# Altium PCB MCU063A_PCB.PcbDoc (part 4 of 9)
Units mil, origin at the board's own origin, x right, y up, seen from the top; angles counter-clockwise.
Board outline 4165.01 x 2371.03 mil, 10 copper layers (Top Layer, Internal Plane 2, Signal Layer 3, Signal Layer 4, Internal Plane 5, Internal Plane 6, Signal Layer 7, Signal Layer 8, Internal Plane 9, Bottom), stack 59.9 mil thick; 436 components, 392 nets, 1750 pads, 1250 vias.
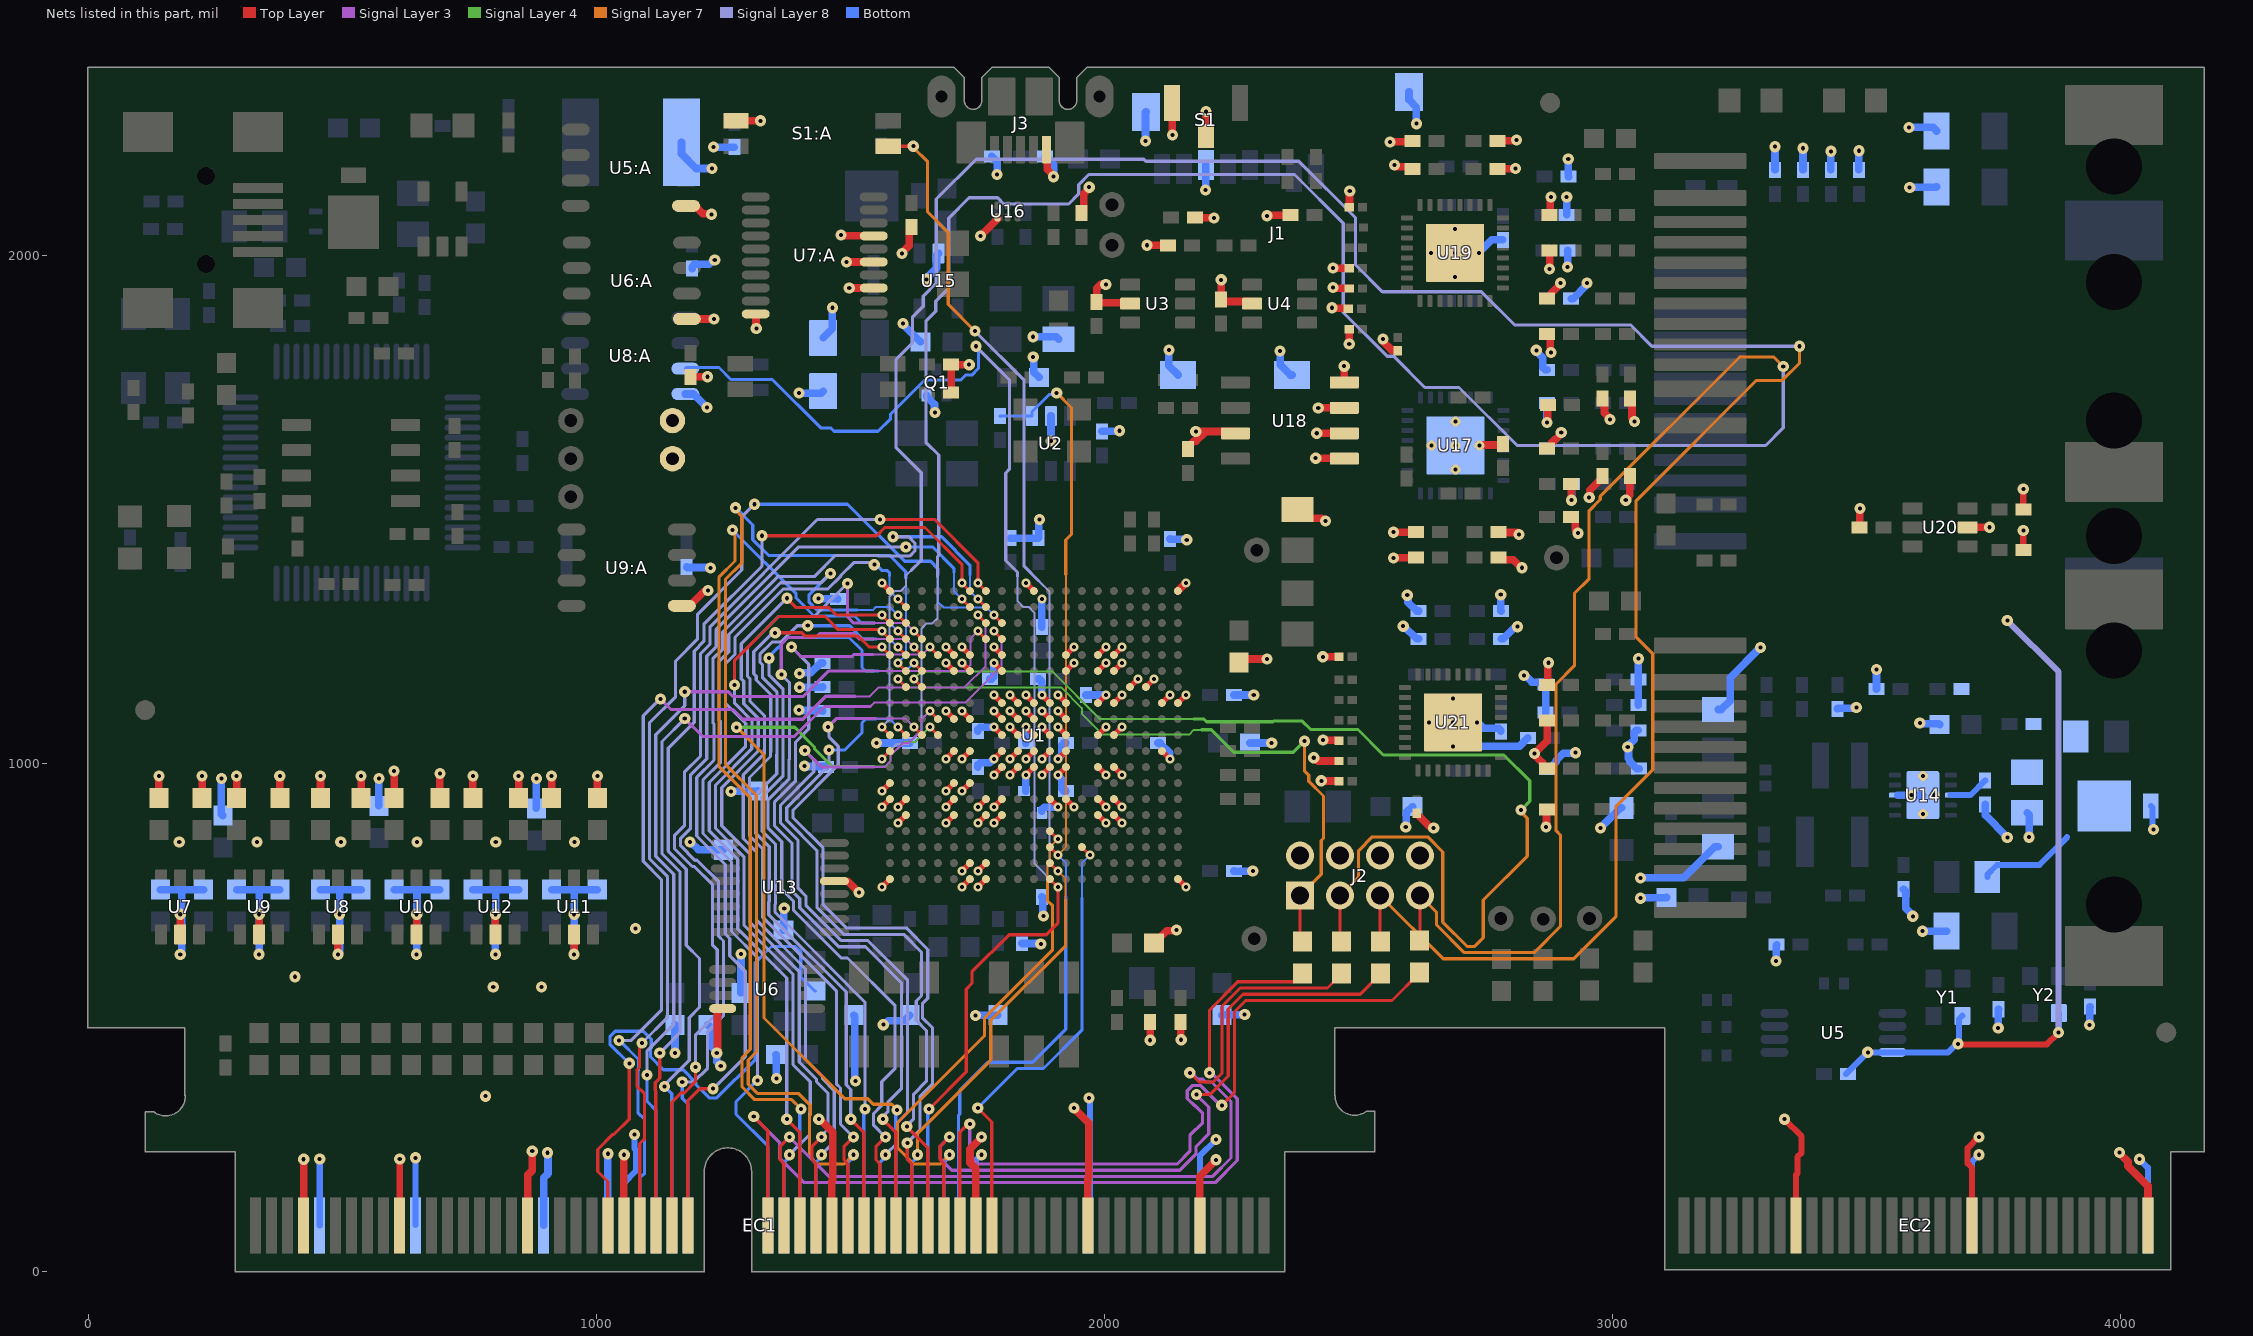
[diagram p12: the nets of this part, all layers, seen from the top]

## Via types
v1: diameter 22, hole 8, Top Layer to Bottom, tented both sides, 895 vias
v2: diameter 18, hole 8, Top Layer to Bottom, tented both sides, 334 vias
v3: diameter 19.68, hole 7.87, Top Layer to Bottom, 19 vias
v4: diameter 18/18/18/18/18/18 (per signal layer), hole 8, Top Layer to Bottom, tented both sides, 1 vias
v5: diameter 22/22/22/22/22/22 (per signal layer), hole 8, Top Layer to Bottom, tented both sides, 1 vias

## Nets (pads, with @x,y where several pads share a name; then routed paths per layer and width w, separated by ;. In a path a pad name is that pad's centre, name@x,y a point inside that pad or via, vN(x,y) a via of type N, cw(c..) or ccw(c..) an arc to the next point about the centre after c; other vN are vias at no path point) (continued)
GND: C1.2 C2.2 C3.2 C4.2 C5.2 C6.2 C7.2 C8.2 C9.2 C10.2 C11.2 C12.2 C13.2 C14.2 C15.2 C16.2 C17.2 C18.2 C19.2 C20.2 C21.2 C21:A.2 C22.2 C23.2 C23:A.2 C24.2 C24:A.1 C25.2 C26.2 C26:A.2 C27.2 C28.2 C28:A.2 C29.2 C29:A.1 C30.2 C31.2 C32.2 C33.2 C34.2 C35.2 C36.2 C37.2 C38.2 C39.2 C40.2 C41.2 C42.2 C43.2 C44.1 C45.2 C46.2 C47.2 C48.2 C49.1 C51.2 C52.1 C53.1 C54.2 C55.2 C56.2 C57.2 C58.2 C59.2 C60.2 C61.2 C62.2 C63.1 C64.1 C65.2 C66.2 C67.2 C68.2 C69.2 C70.2 C71.2 C72.2 C73.2 C74.2 C75.2 C76.2 C77.2 C78.2 C79.2 C80.2 C81.1 C82.2 C83.2 C84.2 C85.2 C86.1 C87.2 C88.2 C89.2 C90.2 C91.2 C92.2 C93.2 C94.2 C95.2 C96.2 C97.1 C98.1 C99.1 C100.1 C101.2 C102.2 C103.1 C104.2 C105.2 C106.2 C107.2 C108.2 C109.2 C110.2 C111.2 C112.2 C113.2 C114.1 C115.2 C116.1 C117.1 C118.1 C119.2 C120.2 C121.1 C122.2 C123.2 C124.2 C125.2 C126.2 C127.2 C128.2 C129.2 C130.2 C131.2 C132.1 C133.1 C134.2 C135.1 C136.1 C137.2 C138.2 C139.1 D5.1 EC1.7 EC1.10 EC1.19 EC1.22 EC1.35 EC1.38 EC1.46 EC1.47 EC1.65 EC1.83 EC1.97 EC1.111 EC2.135 EC2.157 EC2.179 J1.6 J1.S1 J1.S2 J1.S3 J1.S4 J2.2 J2.4 J2.6 J2.8 J3.5 Q1.2 R16.1 R17.1 R18.1 R29.2 R30.1 R38.2 R42.2 R43.2 R88.1 R89.1 R90.1 R96.1 R101.2 R102.2 R105.2 R120.2 R127.1 R128.1 R129.1 R130.1 R131.1 R132.1 R139.2 R140.2 R144.2 R151.1 R152.1 R153.1 R154.1 R155.1 S1.2 S1.3 S1:A.1 TP10.1 U1.A1 U1.A10 U1.A19 U1.E5 U1.E6 U1.E8 U1.E12 U1.E14 U1.E15 U1.F5 U1.F6 U1.F8 U1.F12 U1.F14 U1.F15 U1.G16 U1.G17 U1.H8 U1.H9 U1.H10 U1.H11 U1.H12 U1.H14 U1.H15 U1.H18 U1.H19 U1.J5 U1.J6 U1.J8 U1.J9 U1.J10 U1.J11 U1.J12 U1.K8 U1.K9 U1.K10 U1.K11 U1.K12 U1.K14 U1.K15 U1.L5 U1.L6 U1.L8 U1.L9 U1.L10 U1.L11 U1.L12 U1.L18 U1.M8 U1.M9 U1.M10 U1.M11 U1.M12 U1.M14 U1.M15 U1.N1 U1.N5 U1.N6 U1.P1 U1.P2 U1.P5 U1.P7 U1.P8 U1.P11 U1.P12 U1.P14 U1.P15 U1.R2 U1.R5 U1.R7 U1.R8 U1.R14 U1.R15 U1.V6 U1.V7 U1.W1 U1.W6 U1.W7 U1.W19 U2.2 U3.2 U4.2 U5.4 U5:A.5 U6.4 U6:A.5 U7.2 U7:A.10 U7:A.13 U7:A.15 U7:A.17 U8.2 U8:A.4 U9.2 U9:A.5 U10.2 U11.2 U12.2 U13.13 U14.8 U14.11 U15.2 U16.4 U17.33@2691.07,1626.06 U18.1 U18.2 U18.3 U18.4 U18.7 U19.33@2690.01,2005 U20.2 U21.33@2686.07,1081.06 Y1.2 Y2.2 | length 16818.5
  Top Layer w10: v2(1562.21,756.89) U1.W1@1577.96,772.63 ; v2(1562.21,914.37) U1.P1@1577.96,930.12 ; v2(1562.21,945.86) U1.N1@1577.96,961.61 ; v2(1562.21,1355.31) U1.A1@1577.96,1339.56 ; v2(1593.7,882.87) U1.R2@1609.45,898.62 ; v2(1593.7,914.37) U1.P2@1609.45,930.12 ; v2(1688.19,882.87) U1.R5@1703.94,898.62 ; v2(1688.19,914.37) U1.P5@1703.94,930.12 ; v2(1688.19,945.86) U1.N5@1703.94,961.61 ; v2(1688.19,1008.86) U1.L5@1703.94,1024.6 ; v2(1688.19,1103.34) U1.J5@1703.94,1087.6 ; v2(1688.19,1197.83) U1.F5@1703.94,1182.08 ; v2(1688.19,1229.33) U1.E5@1703.94,1213.58 ; v2(1719.69,756.89) U1.W6@1735.44,772.63 ; v2(1719.69,788.38) U1.V6@1735.44,804.13 ; v2(1719.69,945.86) U1.N6@1735.44,961.61 ; v2(1719.69,1008.86) U1.L6@1735.44,1024.6 ; v2(1719.69,1103.34) U1.J6@1735.44,1087.6 ; v2(1719.69,1197.83) U1.F6@1735.44,1182.08 ; v2(1719.69,1229.33) U1.E6@1735.44,1213.58 ; v2(1751.18,756.89) U1.W7@1766.93,772.63 ; v2(1751.18,788.38) U1.V7@1766.93,804.13 ; v2(1751.18,882.87) U1.R7@1766.93,898.62 ; v2(1751.18,914.37) U1.P7@1766.93,930.12 ; v2(1782.68,882.87) U1.R8@1798.43,898.62 ; v2(1782.68,914.37) U1.P8@1798.43,930.12 ; v2(1782.68,977.36) U1.M8@1798.43,993.11 ; v2(1782.68,1008.86) U1.L8@1798.43,1024.6 ; v2(1782.68,1071.85) U1.K8@1798.43,1056.1 ; v2(1782.68,1103.34) U1.J8@1798.43,1087.6 ; v2(1782.68,1134.84) U1.H8@1798.43,1119.09 ; v2(1782.68,1197.83) U1.F8@1798.43,1182.08 ; v2(1782.68,1229.33) U1.E8@1798.43,1213.58 ; v2(1814.18,977.36) U1.M9@1829.92,993.11 ; v2(1814.18,1008.86) U1.L9@1829.92,1024.6 ; v2(1814.18,1071.85) U1.K9@1829.92,1056.1 ; v2(1814.18,1103.34) U1.J9@1829.92,1087.6 ; v2(1814.18,1134.84) U1.H9@1829.92,1119.09 ; v2(1845.67,977.36) U1.M10@1861.42,993.11 ; v2(1845.67,1008.86) U1.L10@1861.42,1024.6 ; v2(1845.67,1071.85) U1.K10@1861.42,1056.1 ; v2(1845.67,1103.34) U1.J10@1861.42,1087.6 ; v2(1845.67,1134.84) U1.H10@1861.42,1119.09 ; v2(1845.67,1355.31) U1.A10@1861.42,1339.56 ; v2(1877.17,977.36) U1.M11@1892.92,993.11 ; v2(1877.17,1008.86) U1.L11@1892.92,1024.6 ; v2(1877.17,1071.85) U1.K11@1892.92,1056.1 ; v2(1877.17,1103.34) U1.J11@1892.92,1087.6 ; v2(1877.17,1134.84) U1.H11@1892.92,1119.09 ; U1.P11@1892.92,930.12 v2(1908.66,914.37) ; v2(1908.66,977.36) U1.M12@1924.41,993.11 ; v2(1908.66,1008.86) U1.L12@1924.41,1024.6 ; v2(1908.66,1071.85) U1.K12@1924.41,1056.1 ; v2(1908.66,1103.34) U1.J12@1924.41,1087.6 ; v2(1908.66,1134.84) U1.H12@1924.41,1119.09 ; U1.P12@1924.41,930.12 v2(1940.16,914.37) ; U1.F12@1924.41,1182.08 v2(1940.16,1197.83) ; U1.E12@1924.41,1213.58 v2(1940.16,1229.33) ; U1.R14@1987.4,898.62 v2(2003.15,882.87) ; U1.P14@1987.4,930.12 v2(2003.15,914.37) ; U1.M14@1987.4,993.11 v2(2003.15,977.36) ; U1.K14@1987.4,1056.1 v2(2003.15,1071.85) ; U1.H14@1987.4,1119.09 v2(2003.15,1134.84) ; U1.F14@1987.4,1182.08 v2(2003.15,1197.83) ; U1.E14@1987.4,1213.58 v2(2003.15,1229.33) ; U1.R15@2018.9,898.62 v2(2034.65,882.87) ; U1.P15@2018.9,930.12 v2(2034.65,914.37) ; U1.M15@2018.9,993.11 v2(2034.65,977.36) ; U1.K15@2018.9,1056.1 v2(2034.65,1071.85) ; U1.H15@2018.9,1119.09 v2(2034.65,1134.84) ; U1.F15@2018.9,1182.08 v2(2034.65,1197.83) ; U1.E15@2018.9,1213.58 v2(2034.65,1229.33) ; U1.G16@2050.4,1150.59 v2(2066.14,1166.34) ; U1.G17@2081.89,1150.59 v2(2097.64,1166.34) ; U1.L18@2113.39,1024.6 v2(2129.14,1008.86) ; U1.H18@2113.39,1119.09 v2(2129.14,1134.84) ; U1.W19@2144.88,772.63 v2(2160.63,756.89) ; U1.H19@2144.88,1119.09 v4(2160.63,1134.84)
  Top Layer w12: EC1.19@613.19,91 v1(613.19,221.82) ; v1(3338.36,300) 3372.21,266.15 3372.21,233.97 3363.9,225.66 3363.9,193.01 3361.13,190.24 EC2.135@3361.13,91 EC2.135@3363.9,93.77 ; v1(3680.21,448.31) 3681.21,447.31 3855.21,447.31 v1(3878.21,470.31) ; EC2.157@3707.59,91 3707.59,204.93 3699.21,213.31 3699.21,242.9 v1(3721.31,265) ; R139.2@3808.63,1420 v1(3808.63,1458.62) ; R140.2@3808.63,1500 v1(3808.63,1540.62)
  Top Layer w15: C33.2@139.21,931.81 v1(139.21,975.31) ; U7.2@181.02,663.74 181.02,703.12 v1(181.21,703.31) ; C17.2@224.21,931.81 v1(224.21,975.31) ; C37.2@292.21,931.81 v1(292.21,975.31) ; U9.2@336.42,663.74 v1@336.42,703.12 ; C21.2@377.21,931.81 v1(377.21,975.31) ; EC1.7@424.22,91 v1(424.22,221.21) ; C35.2@457.21,931.81 v1(457.21,975.31) ; v1(491.42,624.5) U8.2@491.42,663.74 ; C19.2@537.21,931.81 v1(537.21,975.31) ; C39.2@602.21,931.81 v1(602.21,985.31) ; U10.2@646.42,663.74 v1@646.42,703.12 ; C23.2@692.21,931.81 v1(692.21,980.31) ; C43.2@757.21,931.81 v1(757.21,975.31) ; U12.2@801.42,663.74 v1@801.42,703.12 ; C27.2@847.21,931.81 v1(847.21,975.31) ; EC1.35@865.16,91 865.16,190.15 874.01,199 v1(874.01,237) ; C41.2@912.21,931.81 v1(912.21,975.31) ; v1(956.42,624.5) U11.2@956.42,663.74 ; C25.2@1002.21,931.81 v1(1002.21,975.31) ; EC1.47@1054.14,91 1054.14,229.13 v1(1055.01,230) ; U9:A.5@1168.51,1310.32 1184.2,1310.32 1212.86,1338.97 1218.87,1338.97 v1(1220.21,1340.31) ; U5:A.5@1176.68,2097.63 1194.7,2097.63 1210,2082.34 1225.67,2082.34 v1(1227.01,2081) ; U6:A.5@1178.51,1875 v1(1232.01,1875) ; C26:A.2@1185.03,1761.23 v1(1218.78,1761.23) ; v1@1238.55,432.03 1238.55,516.46 1239.8,517.71 U6.4@1248.82,517.71 ; S1:A.1@1275.01,2265 v1(1323.01,2265) ; U7:A.10@1313.87,1884.84 1314.44,1884.27 1314.44,1856.57 v1(1315.01,1856) ; v1(1438.04,300) 1439.86,300 1465.54,274.32 1465.54,180.53 1463.59,178.58 EC1.65@1463.59,91 ; U13.13@1468.7,768.6 1468.85,768.46 1494.74,768.46 1516.89,746.31 v1(1517.21,746.31) ; v1(1482.01,2040) 1483.1,2038.91 1545.63,2038.91 U7:A.17@1546.15,2038.39 ; v1(1492.8,1987.2) U7:A.15@1546.15,1987.2 ; v1(1497.99,1936.02) U7:A.13@1546.15,1936.02 ; v1(1602.01,2004) 1602.01,2005.89 1615.7,2019.58 1615.7,2052.07 C24:A.1@1620.01,2056.38 ; R29.2@1698.63,1730 R30.1@1698.63,1785 v1(1734.01,1785) ; EC1.83@1747.05,91 1747.05,202.96 1735.5,214.51 1735.5,240.61 1758,263.11 v1(1758,265) ; v1(1756.01,2038) 1790.01,2072 U16.4@1790.01,2075 ; J3.5@1886.14,2207.75 1887.49,2206.39 1887.49,2169.41 1900.01,2156.89 v1(1900.01,2155) ; v1(1939.97,322) 1969.48,292.49 1969.48,184.47 1967.52,182.52 EC1.97@1967.52,91 ; C5.2@1955.01,2083.62 1959.32,2087.93 1959.32,2121.53 1970.21,2132.42 v1(1970.21,2134.31) ; v1(2002.87,1942.97) 1992.87,1942.97 1985.01,1935.11 C4.2@1985.01,1908.62 1986.82,1906.81 2049.06,1906.81 U3.2@2050.88,1905 ; v1(2084.01,2020) C3.2@2125.01,2020 ; R16.1@2090.01,491.38 2090.11,491.28 2090.11,455.41 v1(2090.21,455.31) ; C64.1@2097.64,646.65 2098.62,646.65 2122.95,670.97 2140.87,670.97 v1(2142.21,672.31) ; S1.2@2133.08,2300 2133.54,2299.54 2133.54,2237.46 v1(2134.01,2237) ; U1.A19@2144.88,1339.56 v2(2160.63,1355.31) ; R17.1@2150.01,491.38 2150.61,490.78 2150.61,456.91 v1(2151.21,456.31) ; C115.2@2165.01,1618.62 2165.01,1622.56 2177.32,1634.87 2181.26,1634.87 2196.39,1650 2193.02,1653.37 ; R18.1@2178.63,2075 2179.13,2074.5 2215.51,2074.5 v1(2216.01,2074) ; v1(2180.01,1653.37) 2193.02,1653.37 ; EC1.111@2188,91 2188,187.99 v1(2220.01,220) ; S1.3@2200.01,2235.04 v1(2200.01,2283) ; v1(2230.01,1952) C6.2@2230.01,1913.62 2234.32,1909.31 2286.56,1909.31 U4.2@2290.88,1905 ; U18.7@2257.73,1650 2254.36,1653.37 2193.02,1653.37 ; C82.2@2265,1198.5 2272.2,1205.71 v1(2320.3,1205.71) ; v1(2320.01,2078) 2321.01,2079 2365.39,2079 C2.2@2366.39,2080 ; C81.1@2380.01,1500 2397.51,1482.5 2428.12,1482.5 2433.31,1477.31 v1(2435.21,1477.31) ; v1(2412.21,1011.31) 2414.1,1011.31 2420.41,1005 R153.1@2462.02,1005 ; v1(2416.01,1601) 2416.51,1600.5 2471.79,1600.5 U18.1@2472.29,1600 ; v1(2418.01,1650) U18.2@2472.29,1650 ; v1(2421.01,1700) U18.3@2472.29,1700 ; v1(2427.01,966) 2427.51,965.5 2461.52,965.5 R154.1@2462.02,965 ; v1(2430.01,1210) R151.1@2462.02,1210 ; v1(2430.21,1046.31) 2430.86,1045.66 2461.36,1045.66 R152.1@2462.02,1045 ; v1(2448.01,1897) 2449.24,1895.77 2479.24,1895.77 R129.1@2480.01,1895 ; v1(2450.01,1937) 2451.24,1935.77 2481.25,1935.77 R128.1@2482.02,1935 ; v1(2450.01,1975) R132.1@2482.02,1975 ; v1(2472.01,1782) 2472.01,1750.28 U18.4@2472.29,1750 ; v1(2482.02,1825.99) R130.1@2482.02,1855 ; R127.1@2482.02,2095 2482.51,2095.5 2482.51,2126.5 v1(2483.01,2127) ; v1(2548.21,1835.31) 2549.55,1833.97 2549.55,1829.55 2565.22,1813.88 2576.44,1813.88 2577.21,1813.11 R131.1@2577.21,1812.32 ; v1(2562.01,2223) 2563.01,2224 2605.39,2224 C108.2@2606.39,2225 ; v1(2569.21,1404.31) 2569.71,1404.81 2613.08,1404.81 C91.2@2613.58,1405.31 ; v1(2569.21,1455.31) C94.2@2613.58,1455.31 ; v1(2571.21,2178.2) 2573.1,2178.2 2576.99,2174.31 2602.08,2174.31 C111.2@2606.39,2170 ; R155.1@2615.01,902.01 2615.01,901.22 2641.58,874.65 2646.87,874.65 v1(2648.21,873.31) ; v3(2738.32,1626.06) 2739.21,1626.96 2783.35,1626.96 R105.2@2785.01,1628.62 ; C109.2@2773.63,2170 2774.13,2170.5 2808.51,2170.5 v1(2809.01,2171) ; C110.2@2773.63,2225 2774.63,2226 2810.01,2226 v1(2811.01,2227) ; C93.2@2775.83,1405.31 2780.14,1401 2804.62,1401 2820.31,1385.31 v1(2822.21,1385.31) ; C92.2@2775.83,1455.31 2776.33,1454.81 2812.71,1454.81 v1@2813.21,1454.31 ; v1(2869.21,875.31) 2870.3,876.4 2870.3,908.91 C138.2@2871.39,910 ; v1(2871.21,1671.31) 2872.4,1672.5 2872.4,1704.12 C89.2@2873.58,1705.31 ; C137.2@2871.39,990 2867.45,990 2863.14,994.31 2863.14,1000.93 2846.46,1017.61 v1(2846.46,1019.5) 2871.39,1044.43 C131.2@2871.39,1085 ; C130.2@2871.39,1155 2872.87,1156.48 2872.87,1196.97 v1(2874.21,1198.31) ; C88.2@2871.39,1620 2875.32,1620 2879.64,1624.31 2879.64,1629.85 2899.21,1649.42 v1(2899.21,1651.31) ; C120.2@2871.39,1845 2873.36,1845 2877.67,1840.69 2877.67,1810.34 v1(2879.01,1809) ; C119.2@2871.39,1915 2875.32,1915 2879.64,1919.31 2879.64,1925.73 2898.01,1944.11 v1(2898.01,1946) ; v1(2876.39,1973.62) C113.2@2876.39,2010 ; C112.2@2876.39,2080 2877.7,2081.31 2877.7,2113.69 v1(2879.01,2115) ; C90.2@2918.63,1485 2922.57,1485 2926.88,1480.69 2926.88,1460.53 2932.21,1455.21 v1(2932.21,1453.31) ; C87.2@2918.63,1550 2918.92,1549.71 2918.92,1518.6 v1(2919.21,1518.31) ; v1(2954.21,1523.31) 2955.55,1524.65 2955.55,1537.98 2980.01,1562.44 C98.1@2980.01,1566.38 ; C100.1@2980.01,1718.03 2984.32,1713.72 2984.32,1690.09 2995.21,1679.21 v1(2995.21,1677.31) ; v1(3026.21,1518.31) 3026.21,1520.21 3034.13,1528.13 3034.13,1565.5 C99.1@3035.01,1566.38 ; C97.1@3035.01,1718.03 3038.63,1714.41 3038.63,1679.78 3043.21,1675.21 v1(3043.21,1673.31) ; C134.2@3486.39,1465 3486.7,1465.31 3486.7,1501.69 v1(3487.01,1502) ; U20.2@3699.14,1465 v1(3742.01,1465) ; v1(3998.21,234.31) 3998.21,232.42 4014.71,215.92 4014.71,207.81 4054.04,168.47 EC2.179@4054.04,91
  Signal Layer 3 w15: v1(2846.46,1019.5) v1@2849.27,1022.31
  Signal Layer 4 w15: v1(2932.21,1453.31) v1@2932.21,1457.31
  Signal Layer 8 w12: v1(3777.21,1281.31) 3878.21,1180.31 v1(3878.21,470.31)
  Bottom w6.25: EC1.22@644.01,91.68 EC1.22@644.69,91
  Bottom w12: EC1.10@455.71,91 v1(455.71,221.7) ; EC1.22@644.01,91.68 v1(644.01,224) ; C7.2@3459.59,388.6 v1(3502.6,431.61) U5.4@3551.15,431.61 3660.8,431.61 3677.5,448.31 v1(3680.21,448.31) 3682.12,450.23 3682.12,497.15 Y1.2@3688.55,503.58 ; v1(3878.21,470.31) 3878.38,470.48 3878.38,508.41 Y2.2@3878.55,508.58
  Bottom w15: C32.2@142.21,751.81 187.21,751.81 ; v1@184.21,624.31 184.21,748.81 187.21,751.81 ; C16.2@227.21,751.81 187.21,751.81 ; v1(262.21,970.31) 262.21,900.54 C8.2@264.94,897.81 ; C36.2@292.21,751.81 334.71,751.81 ; v1(336.42,624.5) 336.42,750.1 334.71,751.81 ; C20.2@377.21,751.81 334.71,751.81 ; C34.2@457.21,751.81 492.21,751.81 ; v1(491.42,624.5) 494.8,627.88 v1(494.8,703.31) 494.8,749.22 492.21,751.81 ; C18.2@537.21,751.81 492.21,751.81 ; C9.2@572.21,916.81 v1(572.21,970.31) ; C38.2@602.21,751.81 647.21,751.81 ; v1(646.42,624.5) 646.42,703.12 v1(646.61,703.31) 647.21,703.91 647.21,751.81 ; C22.2@692.21,751.81 647.21,751.81 ; C42.2@757.21,751.81 802.21,751.81 ; v1(801.42,624.5) 801.42,703.12 v1(801.61,703.31) 802.21,703.91 802.21,751.81 ; C26.2@847.21,751.81 802.21,751.81 ; C10.2@882.21,911.81 v1(882.21,970.31) ; EC1.38@896.66,91 896.66,184.65 905.01,193 905.01,234 v1(904.01,234) ; C40.2@912.21,751.81 957.21,751.81 ; v1(956.42,624.5) 956.42,703.12 v1(956.61,703.31) 956.61,751.21 957.21,751.81 ; C24.2@1002.21,751.81 957.21,751.81 ; EC1.46@1022.64,91 1022.64,231.63 v1(1023.01,232) ; C14.2@1154.92,485.63 C14.2@1154.92,485.63 1154.97,430.04 v1(1155.01,430) ; C29:A.1@1167.79,2222.63 1167.79,2199.92 1196.71,2171 v1(1228.01,2171) ; U8:A.4@1175.34,1727.37 1191.33,1727.37 1217.7,1701 v1(1218.01,1701) ; C28:A.2@1178.04,1386.69 1178.89,1385.85 1224.16,1385.85 v1(1225.01,1385) ; v1(1184.21,845.31) 1186.1,845.31 1201.3,830.12 C44.1@1250.01,830.12 ; C23:A.2@1188.79,1974.13 1188.79,1978.07 1193.1,1982.38 1222.38,1982.38 1231.31,1991.31 v1(1233.21,1991.31) ; C13.2@1219.92,485.63 1225.97,479.58 1225.97,443.44 1237.21,432.21 v1(1237.21,430.31) 1237.21,412.8 v1(1245.01,405) ; v1(1230.86,2213.15) C21:A.2@1271.96,2213.15 ; v1(1265.01,945) 1265.44,945.43 1317.68,945.43 C30.2@1318.11,945.86 ; C15.2@1284.92,548.62 C15.2@1284.92,548.62 1284.97,624.96 v1(1285.01,625) ; C11.2@1353.43,427.12 1354.22,426.33 1354.22,380.79 v1(1355.01,380) ; C12.2@1368.43,672.12 1369.22,672.91 1369.22,714.21 v1(1370.01,715) ; v1(1399.01,1729) 1442.63,1729 C85.2@1446.43,1732.8 ; v1(1399.21,1105.31) 1400.19,1104.33 1444.61,1104.33 C80.2@1445.59,1103.34 ; v1(1400.01,1150) 1400.3,1150.29 1445.3,1150.29 C78.2@1445.59,1150.59 ; v1(1400.21,1177.31) 1401.55,1178.65 1422.48,1178.65 1441.66,1197.83 C74.2@1445.59,1197.83 ; v1(1410.01,995) 1410.96,994.05 1451.02,994.05 C65.2@1451.97,993.11 ; v1(1437.01,1325) 1437.6,1324.41 1475,1324.41 C71.2@1475.59,1323.82 ; C84.2@1446.43,1837.8 1464.78,1856.15 1464.78,1896.77 v1(1465.01,1897) ; C28.2@1507.09,504.92 1508.67,503.34 1508.67,376.34 v1(1510.01,375) ; v1(1551.36,1040.35) C54.2@1617.33,1040.35 ; v1(1565.01,486) 1566.9,486 1574.4,493.5 1606.12,493.5 1617.33,504.7 C31.2@1617.33,504.92 ; v1(1604.01,1866) 1605.35,1864.66 1605.35,1862.18 1637.53,1830 R101.2@1638.51,1830 ; v1(1650.01,1953) 1650.01,1954.89 1669.66,1974.54 1669.66,1999.82 U15.2@1673.97,2004.13 ; Q1.2@1650.32,1724.41 1650.32,1722.44 1665.67,1707.1 1665.67,1692.34 v1(1667.01,1691) ; v1(1746.21,504.31) 1746.51,504.62 1790.25,504.62 C29.2@1790.55,504.92 ; C61.2@1751.18,993.11 1751.18,997.04 1755.49,1001.36 1774.37,1001.36 1781.87,1008.86 v2(1782.68,1008.86) ; C73.2@1751.18,1063.97 1751.18,1066.96 1755.49,1071.27 1782.11,1071.27 v2(1782.68,1071.85) ; C58.2@1774.81,1166.34 1777.79,1166.34 1782.11,1170.65 1782.11,1197.26 v2(1782.68,1197.83) ; R102.2@1778.62,2195 1789.01,2184.61 v1(1789.01,2159) ; C70.2@1815.01,1443.62 C76.2@1870.01,1443.62 1871.11,1444.72 1871.11,1479.21 v1(1872.21,1480.31) ; C66.2@1837.8,646.65 1838.62,645.83 1874.18,645.83 v1(1875.01,645) ; C62.2@1845.67,945.86 v2(1845.67,977.36) ; C79.2@1845.67,1040.35 v2(1845.67,1071.85) ; v1(1859.51,1840) 1905.01,1840 R96.1@1910.01,1835 ; v1(1860.01,1800) 1861.35,1798.66 1861.35,1770.16 C83.2@1871.51,1760 ; C75.2@1869.29,1166.34 1872.28,1166.34 1876.59,1162.02 1876.59,1135.41 v2(1877.17,1134.84) ; C69.2@1877.17,737.76 1878.67,736.25 1878.67,701.34 v1(1880.01,700) ; C56.2@1877.17,906.49 1877.17,909.48 1881.48,913.79 1908.09,913.79 v2(1908.66,914.37) ; C59.2@1877.17,1268.7 v2(1877.17,1323.82) ; C86.1@1883.62,2195 1900.01,2178.61 v1(1900.01,2155) ; v1(1895.01,1635) U2.2@1895.01,1684.13 ; v2(1908.66,977.36) 1908.66,976.55 1916.16,969.05 1916.16,950.17 1920.47,945.86 C57.2@1924.41,945.86 ; v2(1908.66,1008.86) 1908.66,1009.67 1916.16,1017.17 1916.16,1036.04 1920.47,1040.35 C60.2@1924.41,1040.35 ; C55.2@1963.78,1134.84 v2(2003.15,1134.84) ; C1.2@1995.01,1653.62 1995.7,1654.31 2029.32,1654.31 v1(2030.01,1655) ; v1(2081.01,2225) 2081.01,2281.52 J1.S2@2082.01,2282.52 ; C68.2@2105.51,1040.35 2109.45,1040.35 2128.56,1021.24 2128.56,1010.24 v2@2129.14,1010.24 ; v1(2127.01,1814) 2127.01,1782.79 J1.S3@2145,1764.8 ; C72.2@2129.14,1441.93 2129.94,1441.12 2161.4,1441.12 v1(2162.21,1440.31) ; v1(2199.01,2129) 2199.37,2129.36 2199.37,2177.83 J1.6@2199.73,2178.19 ; C63.1@2231.5,504.92 2232.2,505.62 2275.51,505.62 v1(2276.21,506.31) ; C77.2@2255.12,1134.84 2255.2,1134.92 2293.93,1134.92 v1(2294.01,1135) ; C53.1@2286.62,1040.35 v1(2329.36,1040.35) ; v1(2292.21,788.31) 2292.17,788.35 C67.2@2255.16,788.35 ; v1(2346.01,1812) 2346.01,1784.86 2366.07,1764.8 J1.S4@2369.41,1764.8 ; v1(2588.21,1270.31) 2589.65,1270.31 2614.65,1245.31 C129.2@2618.58,1245.31 ; v1(2593.21,875.31) 2594.55,876.65 2594.55,903.8 2605.75,915 C52.1@2606.51,915 ; v1(2596.21,1331.31) 2597.55,1329.97 2597.55,1317.41 2614.65,1300.31 C126.2@2618.58,1300.31 ; J1.S1@2599.73,2321.89 2599.73,2306.47 2614.21,2291.99 v1(2614.21,2259.31) ; v3(2686.07,1033.82) 2817.09,1033.82 C123.2@2833.58,1050.31 ; v3(2733.32,1081.06) 2734.58,1081.06 2746.25,1069.4 2776.25,1069.4 2780.56,1065.09 R144.2@2780.56,1063.35 ; v3(2737.25,2005) 2762.84,2030.59 R120.2@2784.5,2030.59 ; v1(2780.21,1332.31) 2780.52,1332 2780.52,1300.62 C127.2@2780.83,1300.31 ; C128.2@2780.83,1245.31 2784.77,1245.31 2807.43,1267.97 2811.87,1267.97 v1(2813.21,1269.31) ; v1(2826.21,1173.31) 2828.1,1173.31 2841.79,1159.62 2864.27,1159.62 C125.2@2868.58,1155.31 C124.2@2868.58,1100.31 ; v1(2850.21,1813.31) 2850.21,1811.42 2863.14,1798.49 2863.14,1779.31 2867.45,1775 C101.2@2871.39,1775 ; v1(2871.21,1671.31) 2871.3,1671.4 2871.3,1709.91 C102.2@2871.39,1710 ; C95.2@2871.39,1620 2875.32,1620 2879.64,1624.31 2879.64,1629.85 2899.21,1649.42 v1(2899.21,1651.31) ; C122.2@2871.58,989.31 2875.52,989.31 2889.58,1003.37 2889.58,1006.71 2902.84,1019.97 2925.87,1019.97 v1(2927.21,1021.31) ; C104.2@2909.83,2080 2909.92,2080.09 2909.92,2114.91 v1(2910.01,2115) ; v1(2911.82,1977) C105.2@2911.82,2010 ; v1(2913.01,2190) 2913.32,2189.69 2913.32,2155.31 C106.2@2913.63,2155 ; C107.2@2918.63,1915 2922.57,1915 2948.67,1941.1 2948.67,1944.66 v1(2950.01,1946) ; v1(2919.21,1518.31) 2919.61,1518.71 2919.61,1549.6 C96.2@2920.01,1550 ; v1(2976.21,873.31) 2976.54,873.31 3015.95,912.72 D5.1@3017.92,912.72 ; C133.1@3050.83,1065.31 3046.89,1065.31 3042.58,1061 3042.58,1046.58 3031.55,1035.55 3031.55,1034.21 3033.44,1032.31 3031.55,1030.42 3031.55,1010.11 3034.26,1007.4 3034.26,1004.06 3048.32,990 C135.1@3052.25,990 ; C132.1@3050.83,1115.31 C136.1@3050.83,1165.31 3051.02,1165.5 3051.02,1206.12 v1(3051.21,1206.31) ; v1(3055.01,735) 3055.7,735.69 3105.73,735.69 R90.1@3106.42,736.38 ; v1(3055.01,775) 3140.03,775 3201.42,836.38 C45.2@3207.92,836.38 ; C51.2@3207.92,1106.38 3214.42,1106.38 3231.92,1123.88 3231.92,1169.02 v1(3291.4,1228.5) ; C114.1@3320.01,2168.62 v1(3320.01,2214) ; v1@3321.8,610.9 v1(3322.21,611.31) 3322.21,642.62 R43.2@3323.09,643.5 ; C116.1@3375.01,2168.62 v1(3375.01,2211) ; C117.1@3430.01,2168.62 v1(3430.01,2205) ; R89.1@3442.92,1107.76 3444.04,1108.88 3478.89,1108.88 v1(3480.01,1110) ; C118.1@3485.01,2168.62 v1(3485.01,2206) ; C48.2@3519.29,1146.38 3519.65,1146.74 3519.65,1184.64 v1(3520.01,1185) ; U14.8@3561.99,937.77 U14.11@3610.82,937.77 ; C49.1@3572.92,752.76 3577.23,748.45 3577.23,715.19 3591.21,701.21 v1(3591.21,699.31) ; v1(3584.01,2252) 3630.92,2252 C121.1@3637.92,2245 ; v1(3585.01,2134) 3636.92,2134 C103.1@3637.92,2135 ; v1(3605.01,1080) 3606.35,1078.66 3641.93,1078.66 R88.1@3643.87,1076.71 ; v1(3610.01,670) C139.1@3657.92,670 ; C46.2@3733.73,919.55 3733.73,898.79 3777.21,855.31 v1(3777.21,854.31) ; v1(3759.21,479.31) 3759.61,479.71 3759.61,515.98 R38.2@3760.01,516.38 ; C47.2@3816.2,903.17 3820.01,899.37 v1(3820.01,855) ; v1(3939.21,485.31) 3939.61,485.71 3939.61,520.98 R42.2@3940.01,521.38 ; C67.2@2255.12,788.38 C67.2@2255.16,788.35
  other v1: 782.21,345.31 797.21,560.31 892.21,560.31 407.21,580.31 181.21,624.31 1077.21,675.31 336.61,703.31 179.21,845.31 332.21,845.31 497.21,845.31 647.21,845.31 802.21,845.31 957.21,845.31 3030.21,1032.31 2816.3,1450.6
  other v3: 3610.82,900.37 3588.19,937.77 3633.46,937.77 3610.82,975.17 2638.83,1081.06 2686.07,1081.06 2686.07,1128.31 2691.07,1578.82 2643.83,1626.06 2691.07,1626.06 2691.07,1673.31 2690.01,1957.76 2642.77,2005 2690.01,2005 2690.01,2052.24
HSEC_5V0: D3.2 EC1.48 EC1.84 EC1.98 EC1.112 EC2.158 EC2.180 TP7.1 | length 1103.2
  Bottom w6.25: v1@1967.52,339.55 v1(1969.97,342)
  Bottom w12: EC1.48@1054.14,91 1054.14,174.13 1078.01,198 1078.01,239.53 1075.01,242.53 v1(1075.01,270) ; EC1.84@1747.05,91 1747.05,219.05 v1(1758,230) ; EC1.98@1967.52,91 1971.48,94.95 1971.48,340.49 v1(1969.97,342) ; EC1.112@2188,91 2188,227.99 v1(2220.01,260) ; EC2.158@3707.59,91 3707.59,216.28 v1(3721.31,230) ; v1(4037.21,221.31) 4054.04,204.47 EC2.180@4054.04,91 ; D3.2@4059.71,916.38 4063.1,913 4063.1,871.91 v1(4065.01,870)
HSEC_ADC-VREFHI: EC1.45 R44.1 | length 1211.2
  Top Layer w6.25: EC1.45@1022.64,91 1022.64,177.37 1002.88,197.13 1002.88,240.34 1032.55,270 1035.01,270 1065.01,300 v1(1065.01,410)
  Bottom w6.25: v1(1065.01,410) 1064.38,410 1026.88,447.49 1026.88,462.51 1037.5,473.13 1092.52,473.13 1108.13,457.51 1108.13,440.63 1106.88,439.38 1106.88,422.49 1132.1,397.28 1170.87,397.28 1196.08,372.07 1196.08,368.29 1222.5,341.88 1237.52,341.88 1312.75,417.11 1312.75,607.74 1344.96,639.95 1391.89,639.95 1402.61,629.23 1402.61,579.95 1430.44,552.12 R44.1@1431.42,552.12
HSEC_GPIO8: EC1.57 R19.2 | length 1800.5
  Top Layer w6.25: v1(1310.01,305) 1337.6,277.41 EC1.57@1337.6,91 ; v1(2207.21,391.31) 2207.21,514.92 2262.74,570.45 2374.43,570.45 2390.01,586.02 R19.2@2390.01,587.01
  Signal Layer 3 w6.25: v1(1310.01,305) 1361.16,253.85 1361.16,223.26 1409.29,175.13 2218.09,175.13 2261.58,218.62 2261.58,339.89 2210.16,391.31 v1(2207.21,391.31)
HSEC_GPIO9: EC1.59 R21.2 | length 1789.5
  Top Layer w6.25: EC1.59@1369.1,91 1369.1,212.49 1361.92,219.66 1361.92,246.88 v1(1380.05,265) ; v1(2168.21,391.31) 2186.33,373.19 2214.71,373.19 2231.59,390.06 2231.59,521.98 2267.81,558.2 2439.31,558.2 2467.14,586.02 R21.2@2467.14,587.01
  Signal Layer 3 w6.25: v1(1380.05,265) 1457.67,187.38 2213.02,187.38 2249.33,223.69 2249.33,334.82 2210.96,373.19 2199.29,373.19 2193.79,378.69 2184.4,378.69 2171.77,391.31 v1(2168.21,391.31)
HSEC_GPIO26: EC1.79 R22.2 | length 1437.1
  Top Layer w6.25: EC1.79@1684.06,91 1684.06,212.49 1676.88,219.66 1676.88,246.88 v1(1695.01,265) ; v1(2181.21,348.31) 2207.16,348.31 2243.84,384.99 2243.84,516.9 2272.89,545.95 2503.5,545.95 2543.57,586.02 R22.2@2543.57,587.01
  Signal Layer 3 w6.25: v1(1695.01,265) 1676.88,246.88 1676.88,222.49 1699.75,199.63 2148.54,199.63 2180.65,231.74 2180.65,246.27 2205.58,271.21 2205.58,323.94 v1(2181.21,348.31)
HSEC_GPIO27: EC1.81 R23.2 | length 1545.1
  Top Layer w6.25: EC1.81@1715.56,91 1715.56,274.45 1731.42,290.31 v1(1735.21,290.31) ; v1(2231.21,327.31) 2256.09,352.2 2256.09,511.83 2277.96,533.7 2566.19,533.7 2620.01,587.52 R23.2@2620.01,588.5
  Signal Layer 3 w6.25: v1(1735.21,290.31) 1735.21,227.16 1750.49,211.88 2143.46,211.88 2168.4,236.81 2168.4,268.07 2193.33,293.01 2193.33,311.82 2178.84,326.31 2177.57,326.31 2163.08,340.8 2163.08,355.82 2173.7,366.44 2188.71,366.44 2227.84,327.31 v1(2231.21,327.31)
IN_5V0: C46.1 C47.1 D3.1 R79.1 R81.2 R82.1 R87.2 U14.3 | length 272.4
  Bottom w12: U14.3@3665.94,937.77 3704.7,937.77 C46.1@3733.73,966.8 ; R82.1@3737.92,776.38 3737.92,781.31 3756.92,800.31 3840.32,800.31 3895.01,855
MCU_GPIO0: EC1.49 U1.C8 | length 2165.1
  Top Layer w6.25: 1085.13,440.13 1085.13,401.66 1080.01,396.54 1080.01,365 1095.13,349.88 1095.13,261.66 1085.64,252.16 EC1.49@1085.64,91 ; v2(1782.68,1292.32) U1.C8@1798.43,1276.57
  Signal Layer 8 w6.25: v1(1090.01,450) 1140.38,500.38 1140.38,776.88 1104.83,812.43 1104.83,1080.3 1156.08,1131.55 1156.08,1201.86 1199.58,1245.36 1199.58,1294.05 1286.33,1380.8 1286.33,1485.44 v1(1311.21,1510.31)
  Bottom w4: 1672.44,1371.08 1672.44,1318.35 1683.47,1307.32 1767.68,1307.32 v2(1782.68,1292.32)
  Bottom w6.25: v1(1311.21,1510.31) 1494.57,1510.31 1606.89,1398 1658,1398 1672.44,1383.56 1672.44,1371.08
MCU_GPIO1: EC1.51 U1.D8 | length 1844.3
  Top Layer w6.25: EC1.51@1117.13,91 1117.13,355.76 1116.08,356.8 1116.08,371.82 1125.01,380.75 v1(1125.01,430) ; v2(1782.68,1260.82) U1.D8@1798.43,1245.08
  Signal Layer 3 w4: 1539.21,1112.31 1546.73,1119.84 1725.9,1119.84 1797.68,1191.62 1797.68,1245.82 v2(1782.68,1260.82)
  Signal Layer 3 w6.25: v1(1174.21,1088.31) 1209.33,1053.19 1390.04,1053.19 1449.16,1112.31 1539.21,1112.31
  Signal Layer 8 w6.25: v1(1125.01,430) 1164.88,469.88 1164.88,787.03 1129.33,822.58 1129.33,1043.44 v1(1174.21,1088.31)
MCU_GPIO2: EC1.53 U1.A7 | length 1997.5
  Top Layer w6.25: EC1.53@1148.63,91 1148.63,333.62 1167.15,352.14 1173.67,352.14 1195.21,373.68 v1(1195.21,402.31) ; v1(1558.21,1480.31) 1666.21,1480.31 1751.18,1395.34 v2(1751.18,1355.31) U1.A7@1766.93,1339.56
  Signal Layer 8 w6.25: v1(1195.21,402.31) 1195.21,465.55 1238.13,508.48 1238.13,633.38 1228.55,642.97 1228.55,762.09 1193.23,797.41 1189.15,797.41 1153.83,832.73 1153.83,857.89 1173.38,877.45 1173.38,982.95 1205.08,1014.65 1205.08,1216.21 1224.08,1235.21 1224.08,1269.12 1435.28,1480.31 v1(1558.21,1480.31)
MCU_GPIO3: EC1.55 U1.B7 | length 2071.5
  Top Layer w6.25: EC1.55@1180.12,91 1180.12,336.23 1203.9,360 v1(1230.01,360) ; v2(1751.18,1323.82) U1.B7@1766.93,1308.07
  Signal Layer 8 w6.25: v1(1230.01,360) 1293.13,423.13 1293.13,591.24 1262.63,621.74 1262.63,655.68 1253.88,664.43 1253.88,801.27 1197.88,857.27 1197.88,972.8 1231.73,1006.65 1231.73,1078.09 1229.58,1080.23 1229.58,1206.07 1248.58,1225.07 1248.58,1258.97 1357.55,1367.94 1429.2,1367.94 1470.7,1409.44 1554.71,1409.44 1555.96,1408.19 1616.71,1408.19 1627.33,1418.8 1627.33,1433.82 1614.84,1446.31 v1(1584.21,1446.31)
  Bottom w4: 1735.44,1371.08 1735.44,1339.56 v2(1751.18,1323.82)
  Bottom w6.25: v1(1584.21,1446.31) 1679.69,1446.31 1735.44,1390.56 1735.44,1371.08
MCU_GPIO4: EC1.50 U1.C7 | length 1968.4
  Top Layer w6.25: v2(1751.18,1292.32) U1.C7@1766.93,1276.57
  Signal Layer 3 w4: 1509.21,1132.31 1538.47,1132.31 1555.99,1149.84 1724.4,1149.84 1766.18,1191.62 1766.18,1277.32 v2(1751.18,1292.32)
  Signal Layer 3 w6.25: v1(1126.21,1127.31) 1147.08,1106.44 1269.4,1106.44 1288.65,1087.19 1406.71,1087.19 1451.84,1132.31 1509.21,1132.31
  Signal Layer 8 w6.25: v1(1045.01,455) 1068.9,455 1128.13,514.24 1128.13,771.81 1092.58,807.36 1092.58,1093.69 v1(1126.21,1127.31)
  Bottom w6.25: v1(1045.01,455) 1045.64,455 1083.13,417.51 1083.13,395.76 1082.01,394.63 1082.01,313 1095.13,299.88 1095.13,193.74 1085.64,184.24 EC1.50@1085.64,91
MCU_GPIO5: EC1.52 U1.D7 | length 1804.9
  Top Layer w6.25: v2(1751.18,1260.82) U1.D7@1766.93,1245.08
  Signal Layer 3 w4: 1544.21,1182.31 1725.38,1182.31 1736.18,1193.11 1736.18,1245.82 v2(1751.18,1260.82)
  Signal Layer 3 w6.25: v1(1174.21,1141.31) 1259.57,1141.31 1269.01,1131.88 1407.52,1131.88 1457.95,1182.31 1544.21,1182.31
  Signal Layer 8 w6.25: v1(1100.13,387.13) 1100.13,434.49 1152.63,486.99 1152.63,781.96 1117.08,817.51 1117.08,1056.82 1174.21,1113.94 v1(1174.21,1141.31)
  Bottom w6.25: v1(1100.13,387.13) 1100.13,334.88 1117.13,317.88 EC1.52@1117.13,91
MCU_GPIO6: EC1.54 U1.A6 | length 1982.9
  Top Layer w6.25: v1(1326.21,1448.31) 1551.84,1448.31 1567.96,1464.44 1647.08,1464.44 1719.69,1391.83 v2(1719.69,1355.31) U1.A6@1735.44,1339.56
  Signal Layer 8 w6.25: v1(1134.21,364.31) 1134.21,366.94 1182.96,415.69 1182.96,499.83 1203.13,520 1203.13,616.24 1177.13,642.24 1177.13,792.1 1141.58,827.66 1141.58,1030.05 1192.83,1081.3 1192.83,1221.29 1211.83,1240.29 1211.83,1274.19 1326.21,1388.57 v1(1326.21,1448.31)
  Bottom w6.25: v1(1134.21,364.31) 1134.32,364.31 1148.63,350.01 EC1.54@1148.63,91
MCU_GPIO7: EC1.56 U1.B6 | length 1932.2
  Top Layer w6.25: v2(1719.69,1323.82) U1.B6@1735.44,1308.07
  Signal Layer 8 w6.25: v1(1169.21,373.31) 1191.84,373.31 1219.08,400.55 1219.08,472.1 1250.38,503.4 1250.38,650.61 1240.8,660.19 1240.8,767.17 1198.3,809.66 1194.22,809.66 1166.08,837.8 1166.08,852.82 1185.63,872.37 1185.63,977.88 1217.33,1009.58 1217.33,1211.14 1236.33,1230.14 1236.33,1264.04 1398.6,1426.31 v1(1609.21,1426.31)
  Bottom w4: 1703.94,1376.58 1703.94,1339.56 v2(1719.69,1323.82)
  Bottom w6.25: v1(1169.21,373.31) 1169.21,341.31 1180.12,330.4 EC1.56@1180.12,91 ; v1(1609.21,1426.31) 1661.69,1426.31 1703.94,1384.06 1703.94,1376.58
MCU_GPIO8: J2.1 R19.1 U1.G2 | length 1336
  Top Layer w6.25: v2(1593.7,1166.34) U1.G2@1609.45,1150.59 ; J2.1@2385.01,740.12 2385.01,655 R19.1@2390.01,650
  Signal Layer 4 w4: v2(1593.7,1166.34) 1610.2,1149.84 1914.88,1149.84 1955.91,1108.81 1955.91,1097.88 1996.94,1056.85 2166.85,1056.85 2176.31,1066.31 2191.69,1066.31
  Signal Layer 4 w6.25: 2191.69,1066.31 2210.69,1066.31 2254.77,1022.23 2371.86,1022.23 v1(2393.63,1044)
  Signal Layer 7 w6.25: J2.1@2385.01,740.12 2427.07,782.17 2427.07,848.54 2431.33,852.8 2431.33,936.05 2402.33,965.05 2402.33,976.82 2393.63,985.52 v1(2393.63,1044)
MCU_GPIO9: J2.3 R21.1 U1.G3 | length 2324.4
  Top Layer w6.25: v2(1625.2,1166.34) U1.G3@1640.95,1150.59 ; J2.3@2463.75,740.12 2463.75,653.39 R21.1@2467.14,650
  Signal Layer 4 w4: v2(1625.2,1166.34) 1640.2,1181.34 1897.52,1181.34 1991.26,1087.6 2175.21,1087.6
  Signal Layer 4 w6.25: 2175.21,1087.6 2195.59,1087.6 2201,1082.19 2331.71,1082.19 2332.96,1083.44 2389.45,1083.44 2406.01,1066.88 2499.21,1066.88 2549.23,1016.85 2786.3,1016.85 2837.33,965.82 2837.33,925.44 v1(2820.21,908.31)
  Signal Layer 7 w6.25: J2.3@2463.75,740.12 2500.43,776.8 2500.43,828.68 2527.29,855.54 2636.42,855.54 2666.08,825.88 2666.08,687.8 2713.7,640.19 2728.71,640.19 2745.88,657.36 2745.88,731.42 2832.33,817.86 2832.33,891.93 2820.21,904.05 v1(2820.21,908.31) v1@2828.21,908.31
MCU_GPIO10: EC1.61 U1.B2 | length 1740.5
  Top Layer w6.25: v1(1375.05,300) 1400.6,274.45 EC1.61@1400.6,91 ; v2(1593.7,1323.82) U1.B2@1609.45,1308.07
  Signal Layer 8 w6.25: v1(1375.05,300) 1375.05,577.92 1278.38,674.58 1278.38,811.42 1222.38,867.42 1222.38,962.66 1293.88,1034.16 1293.88,1047.75 1294.33,1048.2 1294.33,1078.82 1254.08,1119.07 1254.08,1195.92 1273.08,1214.92 1273.08,1248.82 1367.7,1343.44 1455.96,1343.44 1481.33,1368.8 1481.33,1370.07 1506.7,1395.44 1538.82,1395.44 1542.95,1391.31 v1(1547.21,1391.31)
  Bottom w4: 1577.21,1369 1577.21,1340.31 v2(1593.7,1323.82)
  Bottom w6.25: v1(1547.21,1391.31) 1551.47,1391.31 1563.05,1379.73 1572.79,1379.73 1577.21,1375.31 1577.21,1369
MCU_GPIO11: EC1.63 U1.C1 | length 1640.8
  Top Layer w6.25: v1(1375.21,1325.31) 1393.64,1306.88 1458.01,1306.88 1472.57,1292.32 v2(1562.21,1292.32) U1.C1@1577.96,1276.57 ; EC1.63@1432.09,91 1432.09,212.49 1424.92,219.66 1424.92,246.88 v1(1443.04,265)
  Signal Layer 8 w6.25: v1(1375.21,1325.31) 1285.33,1235.44 1285.33,1166.82 1290.33,1161.82 1290.33,1117.47 1318.83,1088.97 1318.83,1033.4 1318.38,1032.95 1318.38,1024.01 1246.88,952.51 1246.88,877.56 1302.88,821.56 1302.88,687.2 1399.55,590.53 1399.55,412.5 1433.42,378.64 1433.42,373.99 1456.17,351.24 1456.17,280.69 1443.04,267.56 v1(1443.04,265)
MCU_GPIO12: EC1.58 U1.C2 | length 1810.9
  Top Layer w6.25: v2(1593.7,1292.32) U1.C2@1609.45,1276.57
  Signal Layer 8 w6.25: v1(1317.21,376.31) 1317.21,618.44 1266.13,669.51 1266.13,806.34 1210.13,862.34 1210.13,967.73 1243.98,1001.57 1243.98,1083.16 1241.83,1085.3 1241.83,1200.99 1260.83,1219.99 1260.83,1253.89 1362.63,1355.69 1442.58,1355.69 v1(1461.21,1374.31)
  Bottom w4: 1514,1302 1544.38,1302 1550.45,1308.07 1577.96,1308.07 v2(1593.7,1292.32)
  Bottom w6.25: v1(1317.21,376.31) 1275.01,334.11 1275.01,310 1337.6,247.41 EC1.58@1337.6,91 ; v1(1461.21,1374.31) 1460.69,1374.31 1418.88,1332.51 1418.88,1317.49 1434.38,1302 1514,1302
MCU_GPIO13: EC1.60 U1.D1 | length 1621.8
  Top Layer w6.25: v1(1272.21,1154.31) 1272.21,1202.94 1358.7,1289.44 1450.46,1289.44 1476.34,1263.56 1559.47,1263.56 v2(1562.21,1260.82) U1.D1@1577.96,1245.08
  Signal Layer 8 w6.25: v1(1272.21,1154.31) 1272.21,1118.27 1306.58,1083.89 1306.58,1038.47 1306.13,1038.03 1306.13,1029.08 1234.63,957.58 1234.63,872.49 1290.63,816.49 1290.63,682.12 1387.3,585.46 1387.3,407.43 1421.17,373.56 1421.17,312.49 1419.92,311.24 1419.92,269.87 v1(1380.05,230)
  Bottom w6.25: EC1.60@1369.1,91 1369.1,214.05 1385.05,230 v1(1380.05,230)
MCU_GPIO14: EC1.62 U1.D2 | length 1942
  Top Layer w6.25: v2(1593.7,1260.82) U1.D2@1609.45,1245.08
  Signal Layer 7 w6.25: v1(1268.21,1459.31) 1268.21,1455.05 1273.13,1450.12 1273.13,1398.54 1241.83,1367.23 1241.83,993.81 1303.13,932.51 1303.13,437.49 1286.83,421.19 1286.83,363.73 1312,338.56 1384.48,338.56 v1(1403.04,320)
  Bottom w4: 1547.47,1276.57 1577.96,1276.57 v2(1593.7,1260.82)
  Bottom w6.25: v1(1268.21,1459.31) 1393.33,1334.19 1393.33,1325.72 1428.6,1290.45 1508.18,1290.45 1522.06,1276.57 1547.47,1276.57 ; EC1.62@1400.6,91 1400.6,317.55 v1(1403.04,320)
MCU_GPIO15: EC1.64 U1.D3 | length 1744.6
  Top Layer w6.25: v2(1625.2,1260.82) U1.D3@1640.95,1245.08
  Signal Layer 3 w4: 1546.21,1276.31 1609.71,1276.31 v2(1625.2,1260.82)
  Signal Layer 3 w6.25: v1(1494.47,1354.63) 1494.47,1288.53 1506.69,1276.31 1546.21,1276.31
  Signal Layer 8 w6.25: v1(1443.04,230) 1468.42,255.38 1468.42,356.31 1445.67,379.06 1445.67,383.71 1411.8,417.58 1411.8,595.61 1315.13,692.27 1315.13,826.64 1289.29,852.49 1289.29,977.59 1330.63,1018.93 1330.63,1027.88 1331.08,1028.33 1331.08,1094.04 1302.58,1122.54 1302.58,1166.89 1297.58,1171.89 1297.58,1228.32 1358.71,1289.45 1429.29,1289.45 v1(1494.47,1354.63)
  Bottom w6.25: EC1.64@1432.09,91 1432.09,214.05 1448.04,230 v1(1443.04,230)
MCU_GPIO16: EC1.67 U1.E1 | length 1557
  Top Layer w6.25: v1(1352.21,1257.31) 1404.57,1257.31 1410.57,1251.31 1515.02,1251.31 1537,1229.33 v2(1562.21,1229.33) U1.E1@1577.96,1213.58 ; EC1.67@1495.08,91 1495.08,212.49 1487.91,219.66 1487.91,246.88 v1(1506.03,265)
  Signal Layer 8 w6.25: v1(1352.21,1257.31) 1349.19,1254.3 1344.24,1254.3 1309.83,1219.89 1309.83,1176.97 1314.83,1171.97 1314.83,1164.41 1343.33,1135.91 1343.33,1023.25 1342.88,1022.8 1342.88,1013.86 1301.54,972.51 1301.54,857.56 1327.38,831.71 1327.38,697.34 1473.13,551.59 1473.13,368.92 1480.67,361.39 1480.67,290.37 v1(1506.03,265)
MCU_GPIO17: EC1.69 U1.E2 | length 1578.6
  Top Layer w6.25: v1(1501.03,300) 1526.58,274.45 EC1.69@1526.58,91 ; v2(1593.7,1229.33) U1.E2@1609.45,1213.58
  Signal Layer 8 w6.25: v1(1416.21,1271.31) 1395.26,1271.31 1363.13,1239.19 1346.45,1239.19 1322.08,1214.82 1322.08,1199.8 1327.08,1194.8 1327.08,1169.48 1355.58,1140.98 1355.58,1018.18 1355.13,1017.73 1355.13,980.01 1313.79,938.66 1313.79,862.76 1340.46,836.09 1340.46,728.4 1339.63,727.58 1339.63,702.42 1357.43,684.63 1357.54,684.63 1491.88,550.28 1491.88,367.49 1501.03,358.34 v1(1501.03,300)
  Bottom w4: 1551.44,1245.08 1577.96,1245.08 v2(1593.7,1229.33)
  Bottom w6.25: v1(1416.21,1271.31) 1498.69,1271.31 1524.92,1245.08 1551.44,1245.08
MCU_GPIO18: EC1.71 U1.E3 | length 1619.3
  Top Layer w6.25: EC1.71@1558.08,91 1558.08,212.49 1550.9,219.66 1550.9,246.88 v1(1569.03,265) ; v2(1625.2,1229.33) U1.E3@1640.95,1213.58
  Signal Layer 3 w4: 1545.21,1245.31 1609.21,1245.31 v2(1625.2,1229.33)
  Signal Layer 3 w6.25: v1(1364.21,1175.31) 1364.21,1234.94 1377.39,1248.13 1432.13,1248.13 1440,1256 1507,1256 1517.69,1245.31 1545.21,1245.31
  Signal Layer 8 w6.25: v1(1364.21,1175.31) 1380.08,1159.44 1380.08,1008.03 1379.63,1007.58 1379.63,969.86 1338.29,928.51 1338.29,872.91 1364.96,846.24 1364.96,752.28 1388.13,729.1 1388.13,711.16 1481.96,617.33 1494.42,617.33 1588.25,523.51 1588.25,400.31 1561.83,373.89 1561.83,327.17 1545.9,311.24 1545.9,288.13 v1(1569.03,265)
MCU_GPIO19: EC1.73 U1.E4 | length 1650.9
  Top Layer w6.25: v1(1564.03,300) 1589.57,274.45 EC1.73@1589.57,91 ; v2(1656.7,1229.33) U1.E4@1672.44,1213.58
  Signal Layer 3 w4: 1544.19,1214.33 1641.7,1214.33 v2(1656.7,1229.33)
  Signal Layer 3 w6.25: v1(1384.21,1229.31) 1403,1210.52 1502.52,1210.52 1506.33,1214.33 1544.19,1214.33
  Signal Layer 8 w6.25: v1(1384.21,1229.31) 1418.33,1195.19 1418.33,1068.35 1392.33,1042.35 1392.33,1002.96 1391.88,1002.51 1391.88,964.79 1350.54,923.44 1350.54,877.98 1385,843.52 1385,749.56 1400.38,734.18 1400.38,716.23 1477.31,639.31 1529.86,639.31 1600.5,568.67 1600.5,359.97 1574.08,333.55 1574.08,314.32 1564.03,304.26 v1(1564.03,300)
MCU_GPIO20: EC1.68 U1.F2 | length 2287.9
  Top Layer w6.25: v2(1593.7,1197.83) U1.F2@1609.45,1182.08
  Signal Layer 7 w6.25: v1(1274.21,1503.31) 1274.21,1499.05 1286.33,1486.93 1286.33,1394.41 1254.08,1362.16 1254.08,998.88 1315.38,937.58 1315.38,432.42 1299.08,416.12 1299.08,368.8 1317.07,350.81 1397.86,350.81 1421.17,327.51 1421.17,308.76 1419.92,307.51 1419.92,227.49 1435.53,211.88 1487.91,211.88 v1(1506.03,230)
  Bottom w4: v2(1593.7,1197.83) 1609.21,1213.34 1609.21,1365.31
  Bottom w6.25: v1(1274.21,1503.31) 1308.08,1469.44 1308.08,1440.8 1339.45,1409.44 1577.56,1409.44 1609.21,1377.79 1609.21,1365.31 ; EC1.68@1495.08,91 1495.08,214.05 1511.03,230 v1(1506.03,230)
MCU_GPIO21: EC1.70 U1.F3 | length 1610.8
  Top Layer w6.25: v2(1625.2,1197.83) U1.F3@1640.95,1182.08
  Signal Layer 8 w6.25: v1(1340.21,1207.31) 1340.21,1173.68 1367.83,1146.05 1367.83,1013.1 1367.38,1012.66 1367.38,974.94 1326.04,933.59 1326.04,867.83 1352.71,841.16 1352.71,723.33 1351.88,722.51 1351.88,707.49 1362.5,696.88 1362.62,696.88 1529.03,530.47 v1(1529.03,320)
  Bottom w4: 1554.98,1182.08 1609.45,1182.08 v2(1625.2,1197.83)
  Bottom w6.25: v1(1340.21,1207.31) 1340.21,1210.94 1377.39,1248.13 1497.52,1248.13 1523,1222.64 1523,1189 1529.92,1182.08 1554.98,1182.08 ; EC1.70@1526.58,91 1526.58,317.55 v1(1529.03,320)
MCU_GPIO22: EC1.72 U1.J4 | length 1479.4
  Top Layer w6.25: v2(1656.7,1103.34) U1.J4@1672.44,1087.6
  Signal Layer 3 w4: 1546.21,993.31 1567.88,993.31 1578.7,1004.14 1578.7,1015.07 1603.99,1040.35 1614.92,1040.35 1640.2,1065.63 1640.2,1086.85 v2(1656.7,1103.34)
  Signal Layer 3 w6.25: v1(1410.46,1025.67) 1442.82,993.31 1546.21,993.31
  Signal Layer 8 w6.25: v1(1410.46,1025.67) 1428.13,1008 1428.13,983.71 1362.79,918.37 1362.79,883.05 1397.25,848.59 1397.25,754.64 1412.63,739.25 1412.63,721.31 1482.38,651.56 1534.93,651.56 1612.75,573.74 1612.75,354.9 1612.38,354.53 1612.38,312.86 1593.08,293.55 1593.08,254.06 v1(1569.03,230)
  Bottom w6.25: EC1.72@1558.08,91 1558.08,214.05 1574.03,230 v1(1569.03,230)
MCU_GPIO23: EC1.74 U1.K4 | length 1636.2
  Top Layer w6.25: v2(1656.7,1071.85) U1.K4@1672.44,1056.1
  Signal Layer 4 w4: 1546.75,993.86 1568.42,993.86 1578.7,1004.14 1578.7,1015.07 1605.75,1042.12 1626.97,1042.12 v2(1656.7,1071.85)
  Signal Layer 4 w6.25: v1(1276.21,1071.31) 1390.45,1071.31 1429.25,1032.52 1429.25,1029.64 1465.03,993.86 1546.75,993.86
  Signal Layer 7 w6.25: v1(1276.21,1071.31) 1330.21,1017.31 1330.21,499.17 1489.07,340.31 1534.35,340.31 1545.35,329.31 1581.21,329.31 v1(1592.21,318.31)
  Bottom w6.25: EC1.74@1589.57,91 1589.57,317.55 1590.33,318.31 v1(1592.21,318.31)
MCU_GPIO24: EC1.75 U1.K3 | length 1447.1
  Top Layer w6.25: v1(1612.21,253.31) 1612.21,221.35 1621.07,212.49 EC1.75@1621.07,91 ; v2(1625.2,1071.85) U1.K3@1640.95,1056.1
  Signal Layer 3 w4: 1549.21,1088.31 1608.73,1088.31 v2(1625.2,1071.85)
  Signal Layer 3 w6.25: v1(1456.21,1072.31) 1472.21,1088.31 1549.21,1088.31
  Signal Layer 8 w6.25: v1(1456.21,1072.31) 1458.21,1070.3 1458.21,1051.94 1476.33,1033.82 1476.33,997.26 1387.29,908.22 1387.29,893.2 1446.58,833.91 1446.58,722.01 1492.01,676.58 1609.91,676.58 1652.47,634.02 1652.47,538.09 1641.88,527.51 1641.88,499.61 1661.96,479.53 1661.96,369.46 1636.88,344.38 1636.88,277.99 v1(1612.21,253.31)
MCU_GPIO25: EC1.77 U1.K2 | length 1395.4
  Top Layer w6.25: v2(1593.7,1071.85) U1.K2@1609.45,1056.1 ; v1(1611.21,285.31) 1652.56,243.95 EC1.77@1652.56,91
  Signal Layer 8 w6.25: v1(1458.21,1026.31) 1458.21,996.46 1375.04,913.29 1375.04,888.13 1434.33,828.83 1434.33,716.93 1487.45,663.81 1605.36,663.81 1640.22,628.95 1640.22,543.17 1629.63,532.58 1629.63,494.53 1649.71,474.46 1649.71,374.53 1624.63,349.46 1624.63,300.7 1611.21,287.27 v1(1611.21,285.31)
  Bottom w4: 1549.92,1087.6 1577.96,1087.6 v2(1593.7,1071.85)
  Bottom w6.25: v1(1458.21,1026.31) 1488.64,1026.31 1523,1060.67 1523,1080 1530.6,1087.6 1549.92,1087.6
MCU_GPIO26: J2.5 R22.1 U1.K1 | length 5062.1
  Top Layer w6.25: v2(1562.21,1071.85) U1.K1@1577.96,1056.1 ; J2.5@2542.49,740.12 2542.49,651.08 R22.1@2543.57,650
  Signal Layer 7 w6.25: J2.5@2542.49,740.12 2666.92,615.69 2923.96,615.69 3006.88,698.62 3006.88,914.99 3079.33,987.44 3079.33,1216.03 3046.08,1249.28 3046.08,1516.51 3283.6,1754.03 3334.56,1754.03 3368.21,1787.68 v1(3368.21,1821.31)
  Signal Layer 8 w4: v2(1562.21,1071.85) 1577.21,1086.85 1577.21,1328.53 1587.8,1339.12 1598.73,1339.12 1609.47,1349.86 1609.47,1369.58 1620.21,1380.32
  Signal Layer 8 w6.25: 1620.21,1380.32 1639.58,1399.69 1639.58,1572.37 1589.63,1622.32 1589.63,1794.99 1622.13,1827.49 1622.13,1878.52 1643.58,1899.97 1643.58,1919.91 1669.33,1945.66 1669.33,2111.07 1747.64,2189.38 2077.67,2189.38 2081.67,2185.38 2382.92,2185.38 2494.63,2073.66 2494.63,1981.25 2547.2,1928.69 2741.79,1928.69 2807.41,1863.06 3035.9,1863.06 3077.65,1821.31 v1(3368.21,1821.31)
MCU_GPIO27: J2.7 R23.1 U1.L1 | length 5154.7
  Top Layer w6.25: v2(1562.21,1008.86) U1.L1@1577.96,1024.6 ; R23.1@2620.01,651.5 2621.23,652.72 J2.7@2621.23,740.12
  Signal Layer 7 w6.25: J2.7@2621.23,740.12 2653.83,707.51 2653.83,682.73 2708.63,627.94 2846.21,627.94 2897.84,679.57 2897.84,859.05 2889.08,867.8 2889.08,1156.55 2925.08,1192.55 2925.08,1334.55 2954.08,1363.55 2954.08,1497.55 2976.08,1519.55 2976.08,1525.82 3250.39,1800.13 3317.39,1800.13 v1(3336.21,1781.31)
  Signal Layer 8 w4: v2(1562.21,1008.86) 1591.94,1038.58 1613.15,1038.58 1640.2,1065.63 1640.2,1265.54 1650.48,1275.82 1661.41,1275.82 1671.7,1286.11 1671.7,1366.8
  Signal Layer 8 w6.25: 1671.7,1366.8 1671.7,1407.49 1674.21,1410 1674.21,1607.31 1648.88,1632.63 1648.88,1870.62 1668.08,1889.82 1668.08,1909.76 1693.83,1935.51 1693.83,2073.57 1733.7,2113.44 1789.94,2113.44 1802.19,2101.19 1929.71,2101.19 1949.68,2121.15 1949.68,2139.41 1969.64,2159.38 2374.27,2159.38 2470.13,2063.51 2470.13,1887.75 2556.45,1801.44 2569.71,1801.44 2630.96,1740.19 2697.98,1740.19 2812.29,1625.88 3301.52,1625.88 3336.21,1660.57 v1(3336.21,1781.31)
MCU_GPIO28: EC1.76 S1:A.3 U1.V11 | length 2451.8
  Top Layer w6.25: S1:A.3@1575.01,2215 v1(1624.01,2215) ; U1.V11@1892.92,804.13 v2(1908.66,788.38)
  Signal Layer 7 w4: v2(1908.66,788.38) 1923.66,773.38 1923.66,731.77
  Signal Layer 7 w6.25: v1(1624.01,2215) 1624.01,2212.37 1652.08,2184.3 1652.08,2085.39 1692.63,2044.84 1692.63,1903.88 v1(1745.21,1851.31) ; v1(1632.02,230) 1632.02,271.38 1776.58,415.94 1776.58,494.36 1923.66,641.44 1923.66,731.77
  Signal Layer 8 w4: 1871.21,1359.31 1892.17,1338.35 1892.17,804.88 v2(1908.66,788.38)
  Signal Layer 8 w6.25: v1(1745.21,1851.31) 1842.13,1754.38 1842.13,1388.38 1871.21,1359.31
  Bottom w6.25: EC1.76@1621.07,91 1621.07,214.05 1637.02,230 v1(1632.02,230)
MCU_GPIO29: EC1.78 U1.W11 U8:A.3 | length 2712.9
  Top Layer w6.25: v1(1655.01,320) 1728.08,393.07 1728.08,555.86 1739.38,567.17 1739.38,589.88 1812.63,663.13 1885.77,663.13 1908.66,686.02 v2(1908.66,756.89) U1.W11@1892.92,772.63
  Signal Layer 8 w4: 1829.18,1368 1829.18,1319.1 1840.21,1308.07 1851.14,1308.07 1862.17,1297.04 1862.17,803.38 v2(1908.66,756.89)
  Signal Layer 8 w6.25: v1(1747.21,1821.31) 1813.13,1755.38 1813.13,1578.97 1805.88,1571.72 1805.88,1399.57 1829.18,1376.28 1829.18,1368
  Bottom w6.25: U8:A.3@1175.34,1777.37 1177.32,1779.35 1241.57,1779.35 1264.99,1755.94 1346.44,1755.94 1441.69,1660.69 1461.01,1660.69 1467.83,1653.88 1554.52,1653.88 1579.38,1678.74 1579.38,1688.03 1646.01,1754.65 1716.92,1754.65 1726.7,1764.44 1739.08,1764.44 1752.13,1777.49 1752.13,1812.12 1747.21,1817.05 v1(1747.21,1821.31) ; EC1.78@1652.56,91 1652.56,317.55 v1(1655.01,320)
MCU_GPIO30: EC1.80 U1.T11 | length 1042.5
  Top Layer w6.25: U1.T11@1892.92,867.12 v2(1908.66,851.38)
  Signal Layer 7 w4: 1888,773 1888,798 1892.92,802.92 1892.92,835.63 v2(1908.66,851.38)
  Signal Layer 7 w6.25: v1(1695.01,230) 1676.88,211.88 1624.51,211.88 1593.08,243.3 1593.08,293.55 1764.33,464.8 1764.33,499.44 1898.13,633.24 1898.13,720.04 1888,730.18 1888,773
  Bottom w6.25: EC1.80@1684.06,91 1684.06,214.05 1700.01,230 v1(1695.01,230)
MCU_GPIO31: EC1.82 R11.1 U1.U11 U2.1 | length 1966.4
  Top Layer w6.25: U1.U11@1892.92,835.63 v2(1908.66,819.88)
  Signal Layer 7 w4: v2(1908.66,819.88) 1924.21,835.42 1924.21,1372.31
  Signal Layer 7 w6.25: v1(1906.2,1729.44) 1935.33,1700.3 1935.33,1451 1924.21,1439.88 1924.21,1372.31
  Bottom w4: v2(1908.66,819.88) 1924.21,804.34 1924.21,737.31
  Bottom w6.25: EC1.82@1715.56,91 1713.13,91 1713.13,308.13 1715.56,310.55 1715.56,356.66 1770.83,411.94 1858.79,411.94 1924.21,477.36 1924.21,737.31 ; R11.1@1795.01,1683.62 1795.52,1684.13 U2.1@1857.61,1684.13 1857.61,1692.01 1892.02,1726.42 1903.18,1726.42 v1(1906.2,1729.44)
MCU_GPIO32: EC1.85 U1.U13 | length 884.2
  Top Layer w6.25: v1(1750.99,322) 1778.55,294.45 EC1.85@1778.55,91 ; U1.U13@1955.91,835.63 v2(1971.66,819.88)
  Bottom w4: 1956.21,735.31 1956.21,804.43 v2(1971.66,819.88)
  Bottom w6.25: v1(1750.99,322) 1828.68,399.69 1880.23,399.69 1956.21,475.66 1956.21,735.31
